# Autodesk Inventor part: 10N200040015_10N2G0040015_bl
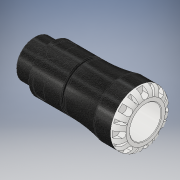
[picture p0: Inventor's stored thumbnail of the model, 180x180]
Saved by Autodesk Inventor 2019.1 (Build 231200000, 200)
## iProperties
Created: 2016-12
Part Number: 10N200040015_10N2G0040015_bl
Material: PVC-Piping
Description: PLASSON MALE ADAPTOR 40X1.1/2" SERIES 1
Document SubType Name: Modeling
Designer: KIM
Mass: 61.7504 g
Surface Area: 140.097 cm^2
Volume: 44.1074 cm^3
Density: 1.4 g/cm^3
Appearance: Black Cast
Author: KIM
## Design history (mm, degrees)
derived "10N20.ipt"
feature "Solid1::10N20.ipt" dims "ScaleForDerivedMember" = 10
tag "TaggingFeature1"
body "Solid1"
other parameters: "d0" = 142 [user parameter], "d1" = 30.66 [user parameter], "d6" = 73 [user parameter], "d8" = 59.5 [user parameter], "d13" = 8 [user parameter], "d14" = 8 [user parameter], "d15" = 0 [user parameter], "d17" = 360 deg [user parameter], "d19" = 8 deg [user parameter], "d20" = 0.8 [user parameter], "d21" = 0.8 [user parameter], "d22" = 8 deg [user parameter], "d24" = 0 [user parameter], "d26" = 360 deg [user parameter], "d32" = 0.925 [user parameter], "d33" = 7 [user parameter], "d34" = 47.803 [user parameter], "d35" = 5 [user parameter], "d38" = 22 [user parameter], "d39" = 1.43409 [user parameter], "d42" = 14 [user parameter], "d43" = 9.2 [user parameter], "d45" = 15.68 [user parameter], "d46" = 0 [user parameter], "d59" = 360 deg [user parameter], "d61" = 11.9 [user parameter], "d62" = 0.8 [user parameter], "d64" = 0 [user parameter], "d65" = 0.7 [user parameter], "d69" = 2 [user parameter], "d70" = 2.13 [user parameter], "d71" = 3 [user parameter], "d73" = 1 [user parameter], "H_" = 142 [user parameter], "l_" = 73 [user parameter], "R_" = 47.803 [user parameter], "l_2" = 22 [user parameter]
